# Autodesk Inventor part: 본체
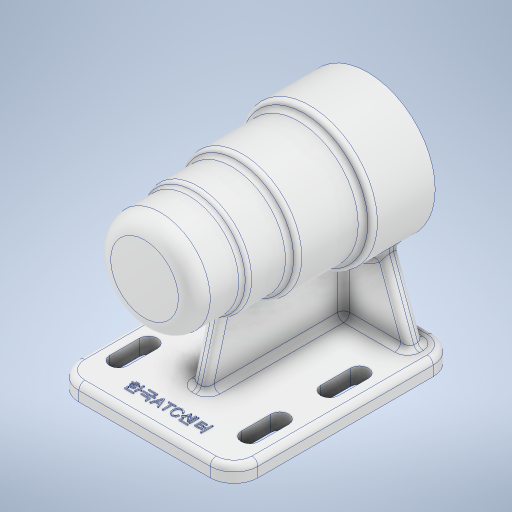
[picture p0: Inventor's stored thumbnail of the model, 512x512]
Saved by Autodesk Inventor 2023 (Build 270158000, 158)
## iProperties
Created: 2022-07
Part Number: 본체
Material: 알루미늄 6061
Document SubType Name: Modeling
Designer: owner
Density: 2.7 g/cm^3
Appearance: 알루미늄 - 평지
Mass: 691.322 g
Surface Area: 698.567 cm^2
Volume: 256.045 cm^3
Author: owner
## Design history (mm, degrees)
sketch "스케치1"
  geometry: L1 (-33, -56)-(33, -56); L2 (45, -44)-(45, 44); L3 (33, 56)-(-33, 56); L4 (-45, 44)-(-45, -44); L5 (-45, -56)-(45, 56); L6 (45, -56)-(-45, 56); A1 r 12 centre (33, 44) between (45, 44) and (33, 56); A2 r 12 centre (-33, 44) between (-33, 56) and (-45, 44); A3 r 12 centre (-33, -44) between (-45, -44) and (-33, -56); A4 r 12 centre (33, -44) between (33, -56) and (45, -44); 1 further point
  constraints: 12 end point, 8 point on circle, 8 point on line, 8 tangent, 4 centre point, 3 equal radius, 2 midpoint, 2 parallel, 1 horizontal, 1 perpendicular
  dimensions: "d0" = 90 distance of L6.end L5.end; "d1" = 112 distance of L5.end L6.start; "d2" = 12 radius of A1
extrude "돌출1" new body sketch "스케치1" distance "d3" = 8; taper "d4" = 0 deg
sketch "스케치2"
  geometry: L1 (70, 56)-(70, -56); L2 (0, 44)-(0, -44) reference; L3 (95, 48)-(95, 32); L4 (95, 32)-(97, 32); L5 (97, 32)-(97, 10); L6 (97, 10)-(100, 10); L7 (100, 10)-(100, -24); L8 (100, -24)-(104, -24); L9 (104, -24)-(104, -56); L10 (104, -56)-(92, -56); L11 (87, 56)-(70, 56); L12 (70, 50)-(77.5, 50); L13 (80.5, 47)-(80.5, 47); L14 (80.5, 47)-(85.7, 47); L15 (86, 46.7)-(86, 43); L16 (86, 43)-(87.2, 43); L17 (87.5, 42.7)-(87.5, 25); L18 (87.5, 25)-(90.7, 25); L19 (91, 24.7)-(91, 13); L20 (91, 13)-(91, 13); L21 (94, 10)-(94, -38); L22 (91, -41)-(91, -41); L23 (91, -41)-(91, -55); L24 (91, -55)-(92, -56); A1 r 8 centre (87, 48) between (95, 48) and (87, 56); A2 r 0.3 centre (85.7, 46.7) between (86, 46.7) and (85.7, 47); A3 r 0.3 centre (87.2, 42.7) between (87.5, 42.7) and (87.2, 43); A4 r 0.3 centre (90.7, 24.7) between (91, 24.7) and (90.7, 25); A5 r 3 centre (77.5, 47) between (80.5, 47) and (77.5, 50); A6 r 3 centre (91, 10) between (94, 10) and (91, 13); A7 r 3 centre (91, -38) between (91, -41) and (94, -38); 8 further points
  constraints: 46 end point, 18 perpendicular, 14 point on circle, 14 tangent, 7 centre point, 6 point on line, 4 equal radius, 2 horizontal, 2 midpoint, 1 horizontal alignment, 1 vertical
  dimensions: "d5" = 70 distance between parallel lines of L2 L1; "d6" = 112 distance of L1.start L1.end; "d7" = 24 distance between parallel lines of L4 L11; "d8" = 46 distance between parallel lines of L6 L11; "d9" = 80 distance between parallel lines of L8 L11; "d10" = 68 diameter of L9 L1; "d11" = 60 diameter of L7 L1; "d12" = 54 diameter of L5 L1; "d13" = 50 diameter of L3 L1; "d14" = 8 radius of A1; "d15" = 21 diameter of L13 L1; "d16" = 32 diameter of L15 L1; "d17" = 35 diameter of L17 L1; "d18" = 3 distance between parallel lines of L14 L12; "d19" = 4 distance between parallel lines of L16 L14; "d20" = 18 distance between parallel lines of L18 L16; "d21" = 12 distance between parallel lines of L20 L18; "d22" = 54 distance between parallel lines of L22 L20; "d23" = 15 distance between parallel lines of L10 L22; "d24" = 48 diameter of L21 L1; "d25" = 42 diameter of L23 L1; "d26" = 42 diameter of L19 L1; "d27" = 0.3 radius of A2; "d28" = 3 radius of A5; "d29" = 1 distance of L23.end point (91, -56); "d30" = 1 distance of L10.end point (91, -56) (= d29)
revolve "회전1" sketch "스케치2" stored, may be unused: angle "d31" = 90 deg
sketch "스케치3"
  geometry: L1 (-33, -21)-(-33, -36); L2 (-37.5, -21)-(-37.5, -36); L3 (-28.5, -36)-(-28.5, -21); L4 (-33, -56)-(33, -56) reference; L5 (-33, 19)-(-33, 4); L6 (-37.5, 19)-(-37.5, 4); L7 (-28.5, 4)-(-28.5, 19); A1 r 4.5 centre (-33, -21) between (-28.5, -21) and (-37.5, -21); A2 r 4.5 centre (-33, -36) between (-37.5, -36) and (-28.5, -36); A3 r 4.5 centre (-33, 19) between (-28.5, 19) and (-37.5, 19); A4 r 4.5 centre (-33, 4) between (-37.5, 4) and (-28.5, 4); 3 further points
  constraints: 16 end point, 8 point on circle, 8 tangent, 4 centre point, 2 midpoint, 2 parallel, 2 vertical
  dimensions: "d32" = 9 diameter of A2; "d33" = 20 distance from line of L4 L1.end; "d34" = 15 distance of L1.start L1.end; "d35" = 33 horizontal distance of point (0, 0) point (-33, -28.5); "d36" = 9 diameter of A4; "d37" = 15 distance of L5.start L5.end; "d38" = 25 distance of L1.start L5.end; "d39" = 33 horizontal distance of point (0, 0) point (-33, 11.5)
extrude "돌출2" cut sketch "스케치3" extent not by distance; stored distance "d40" = 0; taper "d41" = 0 deg
sketch "스케치5"
  geometry: L1 (8, 44)-(8, -44) reference; L2 (43, 32)-(43, 10) reference; L3 (40, 10)-(40, -24) reference; L4 (36, -24)-(36, -56) reference; L5 (43, 19.622)-(8, 29); L6 (8, -44)-(8, 44) reference; L7 (36, -48)-(8, -48); L8 (0, -56)-(8, -56) reference; L9 (8, 29)-(8, -48); L10 (8, -56)-(8, -44) reference; 1 further point
  constraints: 6 end point, 4 point on line, 1 collinear, 1 perpendicular
  dimensions: "d42" = 105 deg angle of L1 L5; "d44" = 8 distance from line of L8 L7.end; "d86" = 77 distance from line of L7 L5.end
feature "리브1" sketch "스케치5" dims "d45" = 1, "d46" = 8, "d47" = 0, "d48" = 0, "d49" = 1, "d50" = 1
node "작업 평면1"
sketch "스케치6"
  geometry: L1 (23.409, 45.342)-(37, 8); L2 (-23.409, 45.342)-(-37, 8); L3 (45, 0)-(45, 8) reference; L4 (-45, 0)-(-45, 8) reference; L5 (45, 8)-(33, 8) reference; L6 (-33, 8)-(-45, 8) reference; L7 (37, 8)-(-37, 8); L8 (-33, 8)-(33, 8) reference; A1 r 34 centre (0, 70) between (23.409, 45.342) and (-23.409, 45.342) reference; 3 further points
  constraints: 6 end point, 2 midpoint, 2 point on circle, 1 coincident, 1 collinear
  dimensions: "d56" = 110 deg angle of L5 L1; "d57" = 110 deg angle of L2 L6; "d58" = 8 distance from line of L2.end L4; "d59" = 8 distance from line of L3 L1.end
extrude "돌출3" join sketch "스케치6" distance "d60" = 8; taper "d61" = 0 deg
fillet "모깎기1" dims "d62" = 3
fillet "모깎기2" dims "d63" = 3
fillet "모깎기3" dims "d64" = 3
fillet "모깎기4" dims "d65" = 3
fillet "모깎기6" dims "d67" = 3
fillet "모깎기7" dims "d68" = 3
fillet "모깎기8" dims "d69" = 3
sketch "스케치7" dims "d77" = 52
  geometry: A1 r 30 centre (0, 0) between (6.364, -29.317) and (-6.364, -29.317) reference; 3 further points
  constraints: 2 horizontal alignment, 1 coincident, 2 other
hole "구멍1" sketch "스케치7" at (-26, 0) diameter "d70" = 3.242; stored, may be unused: countersink angle "d74" = 90 deg, drill point angle "d76" = 118 deg; dims "d71" = 8, "d72" = 4, "d73" = 2, "d75" = 11
sketch "스케치8"
  geometry: L1 (-33, -56)-(33, -56) reference; A1 r 4.5 centre (-33, -36) between (-37.5, -36) and (-28.5, -36) reference; 2 further points
  constraints: 1 vertical alignment, 1 other
  dimensions: "d83" = 12 distance from line of L1 point (0, -44)
feature "엠보싱1" sketch "스케치8" dims "d5" = 70, "d6" = 112, "d7" = 24, "d8" = 46, "d9" = 80, "d10" = 68, "d11" = 60, "d12" = 54, "d13" = 50, "d14" = 8, "d15" = 21, "d16" = 32, "d17" = 35, "d18" = 3, "d19" = 4, "d20" = 18, "d21" = 12, "d22" = 54, "d23" = 15, "d24" = 48, "d25" = 42, "d26" = 42, "d27" = 0.3, "d28" = 3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
node "솔리드1"
mirror "미러1"
pattern_circular "원형 패턴1" dims angle "d79" = 360 deg
feature "A9D066F2-1C7D-4E18-AEED-F7BC21143FA4" dims "d70" = 3.242, "d71" = 8, "d72" = 4, "d73" = 2, "d74" = 90 deg, "d75" = 11, "d76" = 118 deg
other parameters: "d51" = -48
